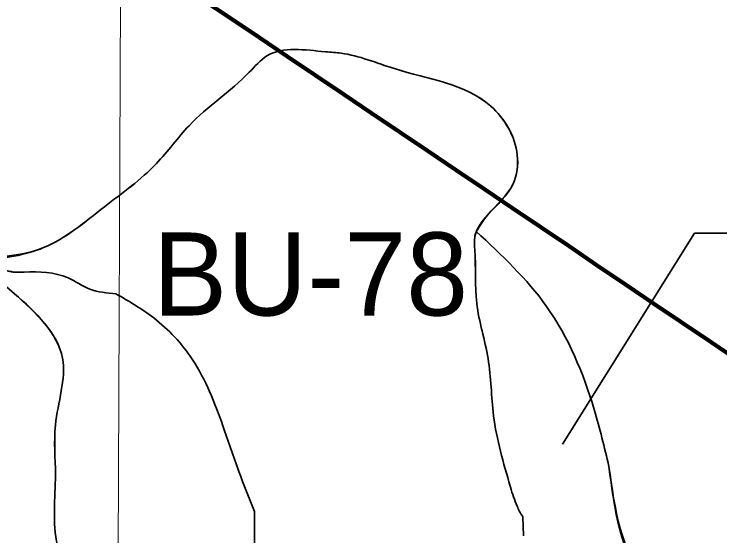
# Model space of a CAD drawing. Extents: x 553962 to 842807, y 8883888 to 9032388.
# Drawn here: x 664180 to 667576, y 8955024 to 8957536 of the extents above; entities that cross this region are included whole.
import ezdxf

# ---------------------------------------------------------------- set-up
doc = ezdxf.new("R2010")
doc.units = 0
doc.header["$LTSCALE"] = 150
for name, color, linetype, lineweight in [('1', 7, 'Continuous', 13), ('20', 7, 'Continuous', 35), ('24', 7, 'Continuous', 25), ('40', 7, 'Continuous', 60), ('9', 7, 'Continuous', 90)]:
    doc.layers.add(name, color=color, linetype=linetype, lineweight=lineweight)

msp = doc.modelspace()

# ---------------------------------------------------------------- linework, layer by layer
at = {"layer": '1'}
msp.add_lwpolyline([(664968.2, 9023436.8), (664657.1, 8949509), (664397.1, 8890880.2)], dxfattribs=at)
at = {"layer": '20'}
for p, q in [((666628, 8955115.8), (666631.4, 8955023.5)), ((666628, 8955115.8), (666631.4, 8955023.5)), ((666631.4, 8955023.5), (666628, 8955115.8))]:
    msp.add_line(p, q, dxfattribs=at)
for points in [[(663981.1, 8956359), (664321.5, 8956411.5), (664614.4, 8956608.1), (664864.3, 8956815.9), (665021.3, 8956998.4), (665311.2, 8957255.6), (665395.6, 8957334.1), (665677.4, 8957354.5), (665753.9, 8957347.5), (666009.5, 8957272.9), (666473.5, 8957092.1), (666601, 8956857), (666580.9, 8956718.8), (666458.2, 8956568.3), (666403.9, 8956491.1)], [(664028.5, 8956347.9), (664321.5, 8956411.5), (664614.4, 8956608.1), (664864.3, 8956815.9), (665021.3, 8956998.4), (665311.2, 8957255.6), (665395.6, 8957334.1), (665677.4, 8957354.5), (665753.9, 8957347.5), (666009.5, 8957272.9), (666473.5, 8957092.1), (666601, 8956857), (666580.9, 8956718.8), (666458.2, 8956568.3), (666395.8, 8956461.5), (666396.3, 8956401), (666405.5, 8956143.7), (666460.3, 8955877.6), (666486.7, 8955602.2), (666567.1, 8955262.4)], [(666402.7, 8956488.5), (666395.8, 8956461.5), (666396.3, 8956401), (666405.5, 8956143.7), (666460.3, 8955877.6), (666486.7, 8955602.2), (666567.1, 8955262.4)], [(666402.7, 8956488.5), (666395.8, 8956461.5), (666396.3, 8956401), (666405.5, 8956143.7), (666460.3, 8955877.6), (666486.7, 8955602.2), (666567.1, 8955262.4)], [(667041.9, 8955358), (666970.7, 8955632.6), (666742.2, 8956127.5), (666403.1, 8956489.3)], [(666403.1, 8956489.3), (666742.2, 8956127.5), (666970.7, 8955632.6), (667041.9, 8955358)], [(658265.6, 8954703.8), (658307.9, 8954697.9), (658477.4, 8954686), (658784.8, 8954711.4), (658906.1, 8954671.9), (659120.4, 8954604.2), (659357.3, 8954511.1), (659671.5, 8954424.1), (659815.3, 8954446.7), (659930.9, 8954686.6), (660012.7, 8954833.3), (660207.3, 8954937.7), (660675.5, 8955107.1), (660909.5, 8955188.9), (660962, 8955262.3), (660987.4, 8955304.6), (661066.3, 8955341.3), (661139.7, 8955386.4), (661204.5, 8955507.8), (661229.9, 8955575.5), (661294.8, 8955586.8), (661382.2, 8955586.8), (661505.5, 8955628), (661660.6, 8955644.9), (661767.7, 8955661.9), (661883.4, 8955724), (661965.2, 8955755), (662010.3, 8955805.8), (662100.5, 8955870.7), (662182.3, 8955930), (662229.4, 8956040), (662460.7, 8956107.8), (662655.3, 8956144.4), (662768.1, 8956169.8), (663129.1, 8956229.1), (663289.8, 8956276.8), (663461.8, 8956276.8), (663617, 8956276.8), (663815.8, 8956271.2), (663900.4, 8956316.3), (663976.5, 8956358.6), (664083.7, 8956324.8), (664176.8, 8956293.7), (664227.5, 8956293.7), (664439.1, 8956265.5), (664543.4, 8956211.9), (664670.3, 8956189.3)], [(664755.7, 8954053.1), (664609.6, 8954383.1), (664511, 8954645), (664477, 8954750.4), (664388.6, 8954978.3), (664378.4, 8955318.5), (664378.4, 8955556.6), (664412.4, 8955879.7), (664181.2, 8956189.3), (663977.3, 8956356)], [(664755.7, 8954053.1), (664609.6, 8954383.1), (664511, 8954645), (664477, 8954750.4), (664388.6, 8954978.3), (664378.4, 8955318.5), (664378.4, 8955556.6), (664412.4, 8955879.7), (664181.2, 8956189.3), (663983, 8956359.5)], [(664755.7, 8954053.1), (664609.6, 8954383.1), (664511, 8954645), (664477, 8954750.4), (664388.6, 8954978.3), (664378.4, 8955318.5), (664378.4, 8955556.6), (664412.4, 8955879.7), (664181.2, 8956189.3), (663983, 8956359.5)], [(663983.2, 8956359), (664083.7, 8956324.8), (664176.8, 8956293.7), (664227.5, 8956293.7), (664439.1, 8956265.5), (664543.4, 8956211.9), (664670.3, 8956189.3)], [(664670.3, 8956189.3), (664543.4, 8956211.9), (664439.1, 8956265.5), (664227.5, 8956293.7), (664176.8, 8956293.7), (664083.7, 8956324.8), (663983.2, 8956359)], [(664669, 8956189.6), (664851.8, 8956072.7), (665036.7, 8955873.9), (665184.2, 8955552.6), (665261, 8955333.8), (665337, 8955141.6)], [(665337, 8955141.6), (665261, 8955333.8), (665184.2, 8955552.6), (665036.7, 8955873.9), (664851.8, 8956072.7), (664669, 8956189.6)], [(664669, 8956189.6), (664851.8, 8956072.7), (665036.7, 8955873.9), (665184.2, 8955552.6), (665261, 8955333.8), (665337, 8955141.6)], [(667387.8, 8954671.3), (667222.4, 8954809.2), (667041.9, 8955358)], [(668451.1, 8953315.8), (668548.3, 8953649.2), (668340.1, 8954010.4), (668194.3, 8954288.3), (667784.7, 8954302.2), (667416.8, 8954649.5), (667222.4, 8954809.2), (667041.9, 8955358)], [(666567.2, 8955262.5), (666568.4, 8955257.9), (666600.3, 8955166.1), (666625.9, 8955118.5), (666627.9, 8955115.8)], [(666567.2, 8955262.5), (666568.4, 8955257.9), (666600.3, 8955166.1), (666625.9, 8955118.5), (666627.9, 8955115.8)], [(666567.2, 8955262.5), (666568.4, 8955257.9), (666600.3, 8955166.1), (666625.9, 8955118.5), (666627.9, 8955115.8)], [(665337, 8955141.6), (665337, 8954849.1), (665367.6, 8954611), (665558, 8954389.9), (665741.6, 8954185.8)], [(665741.6, 8954185.8), (665558, 8954389.9), (665367.6, 8954611), (665337, 8954849.1), (665337, 8955141.6)], [(665741.6, 8954185.8), (665558, 8954389.9), (665367.6, 8954611), (665337, 8954849.1), (665337, 8955141.6)]]:
    msp.add_spline(points, degree=3, dxfattribs=at)
at = {"layer": '24'}
msp.add_spline([(665209.5, 8949437.1), (665261.8, 8949907.3), (665888.8, 8950560.5), (666750.9, 8951187.5), (667665.3, 8951814.5), (668344.5, 8952363.1), (668788.7, 8952911.7), (669180.6, 8953564.9), (669154.4, 8954270.2), (669755.3, 8954662.1), (670486.8, 8955027.9), (671218.3, 8955785.5), (671166.1, 8956360.3), (671531.8, 8956726), (671479.6, 8956987.3), (670957.1, 8957405.3), (670695.8, 8957849.4), (671139.9, 8958502.5), (671845.3, 8959207.9), (672394, 8958789.9), (673047.1, 8959234), (673465.1, 8959834.9), (673177.7, 8960461.9), (673987.6, 8960749.3), (675163.2, 8960879.9), (676103.7, 8960906.1), (677253.2, 8961428.6), (677697.4, 8961559.2), (678115.4, 8962133.9), (678611.8, 8962369.1), (678820.8, 8962919.9), (679291, 8963704.1), (679918, 8964226.8), (679944.1, 8964697.3), (679709, 8965272.3), (679291, 8966004.2), (678115.4, 8966945.2)], degree=3, dxfattribs=at)
at = {"layer": '40', "lineweight": 35}
msp.add_lwpolyline([(666817.7, 8955464.9), (667453.7, 8956480.5), (669497.1, 8956480.5)], dxfattribs=at)
at = {"layer": '9'}
msp.add_spline([(637260.6, 8972975.8), (641524.5, 8971056.2), (652526.1, 8965412.7), (653164.3, 8965062.8), (670790.5, 8953770.1), (686194, 8943929.9), (696283.3, 8937647.1)], degree=3, dxfattribs=at)

# ---------------------------------------------------------------- texts
at = {"layer": '40'}
msp.add_text('BU-78', height=400, dxfattribs=at).set_placement((664847.7, 8956084.5))

doc.saveas('drawing.dxf')
